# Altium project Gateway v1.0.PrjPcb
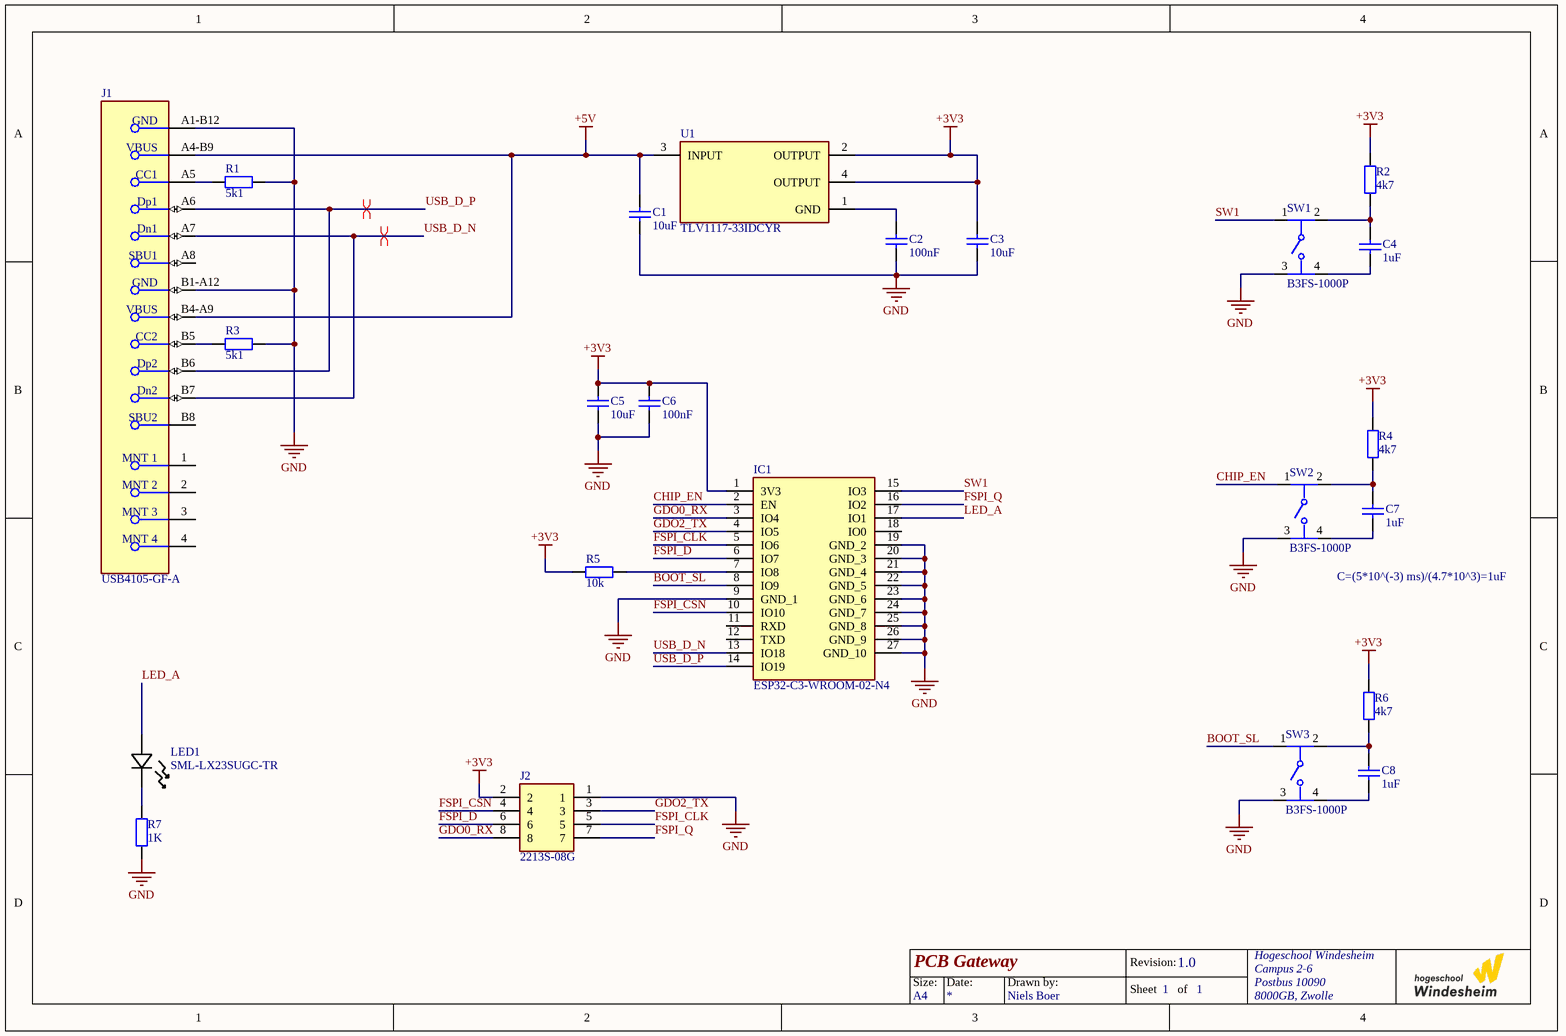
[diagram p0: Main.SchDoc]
1 sheet, 23 parts. Net scope: global (net labels, ports and power ports of the same name join across sheets).

## Sheet Main.SchDoc: PCB Gateway
size A4; DrawnBy: Niels Boer; Revision: 1.0; SheetNumber: 1; SheetTotal: 1; SPICEModelCacheLWGWPIKD: <root> / <DocumentId>LWGWPIKD</DocumentId> / <CacheFrame Number="0"> / <Model Name="smllx23sugctr_yellowled" Kind="MDL"> / <Text>* / * This spice model was created using the Altium Spice Model Wizard / * Created: 20:31 on 02 november, 2022 / * / * Component Name: SMLLX23SUGCTR_yellowLED / * Component Description: Test to add simulation model with XSPICE model command / * / .MODEL SMLLX23SUGCTR_yellowLED D / +( / +     IS = 1.0000E-0014 / +      N = 1.0000 / +     RS = 0.0000 / +)</Text> / </Model> / </CacheFrame> / </root>

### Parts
C1  10uF  [C1206]
C2  100nF  [C1206]
C3  10uF  [C1206]
C4  1uF  [C1206]
C5  10uF  [C1206]
C6  100nF  [C1206]
C7  1uF  [C1206]
C8  1uF  [C1206]
IC1  ESP32-C3-WROOM-02-N4  [ESP32C3WROOM02N4]
J1  USB4105-GF-A  [FP-USB4105-GF-A-MFG]
J2  2213S-08G  [HDRV8W64P254_2X4_1016X508X874P]
LED1  SML-LX23SUGC-TR  [LED_SML-LX23SUGC-TR_LUM]
R1  5k1  [R1206]
R2  4k7  [R1206]
R3  5k1  [R1206]
R4  4k7  [R1206]
R5  10k  [R1206]
R6  4k7  [R1206]
R7  1K  [R1206]
SW1  B3FS-1000P  [FP-B3FS-1000P-MFG]
SW2  B3FS-1000P  [FP-B3FS-1000P-MFG]
SW3  B3FS-1000P  [FP-B3FS-1000P-MFG]
U1  TLV1117-33IDCYR  [FP-DCY0004A-MFG]

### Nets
+3V3: C3.2 C5.2 C6.2 IC1.1(3V3) J2.2 R2.2 R4.2 R5.1 R6.2 U1.2(OUTPUT) U1.4(OUTPUT)
+5V: C1.2 J1.A4-B9(VBUS) J1.B4-A9(VBUS) U1.3(INPUT)
GND: C1.1 C2.1 C3.1 C5.1 C6.1 IC1.9(GND_1) IC1.19(GND_2) IC1.20(GND_3) IC1.21(GND_4) IC1.22(GND_5) IC1.23(GND_6) IC1.24(GND_7) IC1.25(GND_8) IC1.26(GND_9) IC1.27(GND_10) J1.A1-B12(GND) J1.B1-A12(GND) J2.1 R1.2 R3.2 R7.1 SW1.3 SW2.3 SW3.3
BOOT_SL: IC1.8(IO9) SW3.1
CHIP_EN: IC1.2(EN) SW2.1
FSPI_CLK: IC1.5(IO6) J2.5
FSPI_CSN: IC1.10(IO10) J2.4
FSPI_D: IC1.6(IO7) J2.6
FSPI_Q: IC1.16(IO2) J2.7
GDO0_RX: IC1.3(IO4) J2.8
GDO2_TX: IC1.4(IO5) J2.3
LED_A: IC1.17(IO1) LED1.2
SW1: IC1.15(IO3) SW1.1
USB_D_N: IC1.13(IO18) J1.A7(Dn1) J1.B7(Dn2)
USB_D_P: IC1.14(IO19) J1.A6(Dp1) J1.B6(Dp2)
NetC2_2: C2.2 U1.1(GND)
NetC4_1: C4.1 SW1.4
NetC4_2: C4.2 R2.1 SW1.2
NetC7_1: C7.1 SW2.4
NetC7_2: C7.2 R4.1 SW2.2
NetC8_1: C8.1 SW3.4
NetC8_2: C8.2 R6.1 SW3.2
NetIC1_7: IC1.7(IO8) R5.2
NetJ1_A5: J1.A5(CC1) R1.1
NetJ1_B5: J1.B5(CC2) R3.1
NetLED1_1: LED1.1 R7.2

Not connected (* = marked no-connect by the designer): IC1 11(RXD) 12(TXD) 18(IO0); J1 1(MNT_1) 2(MNT_2) 3(MNT_3) 4(MNT_4) A8(SBU1) B8(SBU2)

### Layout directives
differential pair: USB_D_N, USB_D_P

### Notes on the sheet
- C=(5*10^(-3) ms)/(4.7*10^3)=1uF

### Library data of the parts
C1-C8 = Capacitor_1206: SMD Capacitor 1206
IC1 = ESP32-C3-WROOM-02-N4: Integrated Circuit; Manufacturer_Name: Espressif Systems
J1 = CMP-245163-000001-1: CONN RCPT USB2.0 TYPEC 5A; Manufacturer: GCT; Voltage Rating: 20V; Is Female: yes; Current Rating: 5/6.25/1.25/0.25A; Number Of Contacts: 16; Conn Orientation: Right Angle
J2 = 2213S-08G: Connector; Manufacturer_Name: MULTICOMP
LED1 = SML-LX23SUGC-TR: Yellow LED SMD; Mfr_Name: Lumex; Type: DEV
R1-R7 = Resistor_1206: SMD Resistor 1206
SW1-SW3 = CMP-08834-000003-2: SWITCH TACTILE SPST-NO 0.05A 24V; Switch Function: Off-Mom; Max Current Rating: 50mA; Throw Configuration: SPST; Switch Travel: 0.25mm; Number of Poles: 1; Actuator Length: 0.5mm; Ratings: IP00; Mechanical Life: 1000000Cycles; Illumination Type: Non-Illuminated; Actuator Color: Black; Operating Force: 0.98N; Contact Resistance: 100mR; Actuator Type: Standard
U1 = CMP-04917-000056-1: IC REG LIN 3.3V 800MA SOT223-4; Manufacturer: Texas Instruments; Nominal Supply Current: 5mA; Dropout Voltage: 1.2V; Max Supply Voltage: 15V; Min Supply Voltage: 4.7V; Output Type: Fixed; Number Of Outputs: 1; Output Current: 0.8A; Standoff Height: 0.02mm; Max Junction Temp: +125°C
